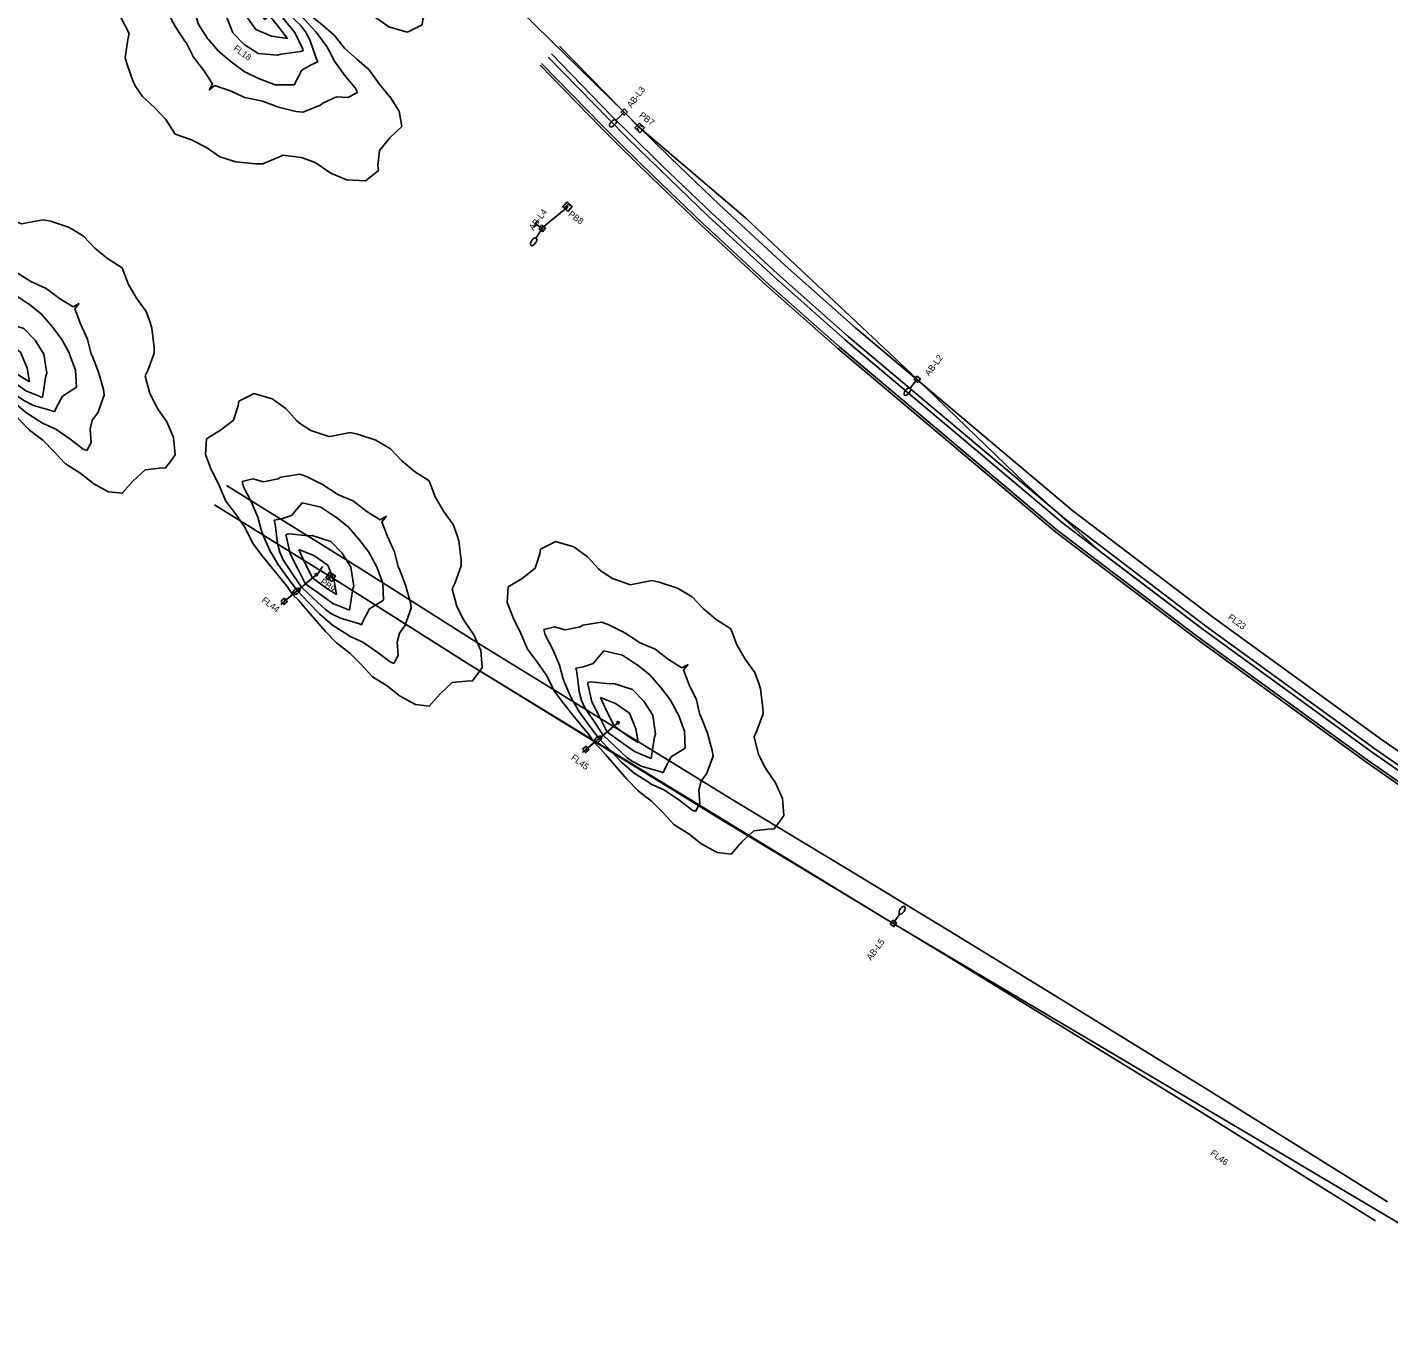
# Model space of a CAD drawing. Extents: x 1322666 to 1327584, y 458075 to 462260.
# Drawn here: x 1325587 to 1326187, y 459186 to 459766 of the extents above; entities that cross this region are included whole.
import ezdxf

# ---------------------------------------------------------------- set-up
doc = ezdxf.new("R2010")
doc.units = 0
for name, color, linetype in [('_CIVIL_CONSTRUCTION', 7, 'Continuous'), ('Default', 7, 'Continuous'), ('DR_P_Culvert', 7, 'Continuous'), ('DR_P_Culvert3D', 7, 'Continuous'), ('DR_X_Cells', 7, 'Continuous'), ('PF_X_Ground_Line', 7, 'Continuous'), ('UT_X_Cable_TV_FO', 7, 'Continuous'), ('UT_X_Misc_Cells', 7, 'Continuous'), ('UT_X_Oil', 7, 'Continuous')]:
    doc.layers.add(name, color=color, linetype=linetype)

# ---------------------------------------------------------------- blocks, each defined once
blk = doc.blocks.new('AGI32-IDj66arb-Project_1-LUMINAIRE-ERL2_19C330______Symbol')
at = {"layer": 'Default'}
for p, q in [((-0.03, 0), (0.03, 0)), ((0, 0.13), (0.24, 0.13)), ((0, -0.13), (0, 0.13)), ((0, 0.13), (0, 0.13)), ((0, 0.13), (0.24, 0.13)), ((0.24, 0.13), (0, 0.13)), ((0, -0.13), (0, 0.13)), ((0, 0.13), (0, 0.13)), ((0, 0.13), (0, -0.13)), ((0.24, 0.13), (0, 0.13)), ((0, 0.13), (0, -0.13)), ((0, -0.03), (0, 0.03)), ((0, 0.03), (0.03, 0)), ((0, -0.03), (0.03, 0)), ((0.24, 0.13), (0.24, -0.13)), ((0.24, 0.13), (0.24, 0.13)), ((0.24, 0.13), (0.24, 0.13)), ((0.24, 0.13), (0.24, -0.13)), ((0.24, -0.13), (0.24, 0.13)), ((0.24, -0.13), (0.24, 0.13)), ((0.24, -0.13), (0, -0.13)), ((0.24, -0.13), (0, -0.13)), ((0, -0.13), (0, -0.13)), ((0, -0.13), (0.24, -0.13)), ((0, -0.13), (0, -0.13)), ((0, -0.13), (0.24, -0.13)), ((0.24, -0.13), (0.24, -0.13)), ((0.24, -0.13), (0.24, -0.13))]:
    blk.add_line(p, q, dxfattribs=at)
blk = doc.blocks.new('AGI32-IDj66arb-Project_1-LUMINAIRE-ERL2_19C330______64-1')
at = {"layer": 'Default'}
blk.add_blockref('AGI32-IDj66arb-Project_1-LUMINAIRE-ERL2_19C330______Symbol', (0, 0), dxfattribs=at)
blk = doc.blocks.new('AGI32-IDj66arb-Project_1-LUMINAIRE-ERL2_19C330______Template1')
at = {"layer": 'Default'}
for p, q in [((9.14, 19.22), (10.58, 20.11)), ((10.58, 20.11), (10.97, 20.5)), ((10.97, 20.5), (12.6, 20.11)), ((12.6, 20.11), (12.8, 20.07)), ((12.8, 20.07), (13.99, 18.29)), ((4.29, 18.29), (5.49, 19.56)), ((5.49, 19.56), (7.31, 19.28)), ((7.31, 19.28), (9.14, 19.22)), ((3.66, 16.46), (4.29, 18.29)), ((13.99, 18.29), (14.48, 16.46)), ((3.25, 14.63), (3.66, 16.45)), ((3.66, 16.45), (3.66, 16.46)), ((14.48, 16.46), (14.57, 14.63)), ((2.69, 12.8), (3.25, 14.63)), ((14.57, 14.63), (14.63, 14.24)), ((14.63, 14.24), (15.08, 12.8)), ((2.59, 10.97), (2.69, 12.8)), ((4.85, 10.97), (5.23, 12.8)), ((5.23, 12.8), (5.49, 13.32)), ((5.49, 13.32), (6.62, 12.8)), ((6.62, 12.8), (7.31, 11.77)), ((15.08, 12.8), (16.17, 10.97)), ((2.44, 9.14), (2.59, 10.97)), ((4.29, 9.14), (4.85, 10.97)), ((7.31, 11.77), (8.8, 10.97)), ((8.8, 10.97), (9.14, 10.91)), ((9.14, 10.91), (10.97, 9.83)), ((16.17, 10.97), (16.46, 10.82)), ((16.46, 10.82), (18.29, 9.79)), ((10.97, 9.83), (11.39, 9.14)), ((18.29, 9.79), (18.8, 9.14)), ((2, 7.31), (2.44, 9.14)), ((3.47, 7.31), (3.66, 7.83)), ((3.66, 7.83), (4.29, 9.14)), ((5.27, 7.31), (5.49, 7.72)), ((5.49, 7.72), (6.19, 7.31)), ((11.39, 9.14), (12.17, 7.31)), ((18.8, 9.14), (19.94, 7.31)), ((1.89, 5.49), (2, 7.31)), ((2.95, 5.49), (3.47, 7.31)), ((4.09, 5.49), (5.27, 7.31)), ((6.19, 7.31), (7.31, 6.87)), ((7.31, 6.87), (9.14, 7.19)), ((9.14, 7.19), (10.42, 5.49)), ((12.17, 7.31), (12.76, 5.49)), ((19.94, 7.31), (20.11, 6.9)), ((20.11, 6.9), (20.59, 5.49)), ((1.86, 3.66), (1.89, 5.49)), ((2.64, 3.66), (2.95, 5.49)), ((3.66, 4.54), (4.09, 5.49)), ((4.43, 3.66), (5.39, 5.49)), ((5.39, 5.49), (5.49, 5.63)), ((5.49, 5.63), (5.75, 5.49)), ((5.75, 5.49), (7.31, 3.9)), ((10.42, 5.49), (10.97, 3.69)), ((12.76, 5.49), (12.8, 5.34)), ((12.8, 5.34), (13.64, 3.66)), ((20.59, 5.49), (20.69, 3.66)), ((1.85, 1.83), (1.86, 3.66)), ((2.53, 1.83), (2.64, 3.66)), ((3.22, 1.83), (3.42, 3.66)), ((3.42, 3.66), (3.66, 4.54)), ((4.03, 1.83), (4.43, 3.66)), ((5.05, 1.83), (5.49, 3.41)), ((5.49, 3.41), (6.36, 1.83)), ((7.31, 3.9), (7.65, 3.66)), ((7.65, 3.66), (8.83, 1.83)), ((10.97, 3.69), (10.98, 3.66)), ((10.98, 3.66), (11.36, 1.83)), ((13.64, 3.66), (14.06, 1.83)), ((20.69, 3.66), (21.05, 1.83)), ((1.83, 1.08), (1.85, 1.83)), ((2.41, 0), (2.53, 1.83)), ((3.01, 0), (3.22, 1.83)), ((3.66, 0.28), (4.03, 1.83)), ((4.62, 0), (5.05, 1.83)), ((6.36, 1.83), (6.85, 0)), ((8.83, 1.83), (8.98, 0)), ((11.36, 1.83), (11.4, 0)), ((14.06, 1.83), (14.63, 0.14)), ((21.05, 1.83), (21.63, 0)), ((1.73, 0), (1.83, 1.08)), ((3.62, 0), (3.66, 0.28)), ((14.63, 0.14), (15.4, 0)), ((1.83, -0.98), (1.73, 0)), ((1.85, -1.83), (1.83, -0.98)), ((2.55, -1.83), (2.41, 0)), ((3.25, -1.83), (3.01, 0)), ((3.66, -0.25), (3.62, 0)), ((4.07, -1.83), (3.66, -0.25)), ((5.07, -1.83), (4.62, 0)), ((6.85, 0), (6.29, -1.83)), ((8.98, 0), (8.72, -1.83)), ((11.4, 0), (11.31, -1.83)), ((14.63, -0.15), (14.04, -1.83)), ((15.4, 0), (14.63, -0.15)), ((21.63, 0), (20.99, -1.83)), ((1.88, -3.66), (1.85, -1.83)), ((2.67, -3.66), (2.55, -1.83)), ((3.47, -3.66), (3.25, -1.83)), ((4.53, -3.66), (4.07, -1.83)), ((5.49, -3.15), (5.07, -1.83)), ((6.29, -1.83), (5.49, -3.15)), ((8.72, -1.83), (7.6, -3.66)), ((11.31, -1.83), (10.97, -3.51)), ((14.04, -1.83), (13.56, -3.66)), ((20.99, -1.83), (20.7, -3.66)), ((1.89, -5.49), (1.88, -3.66)), ((2.97, -5.49), (2.67, -3.66)), ((3.66, -4.38), (3.47, -3.66)), ((4.15, -5.49), (3.66, -4.38)), ((5.49, -5.44), (4.53, -3.66)), ((7.31, -3.83), (5.49, -5.44)), ((7.6, -3.66), (7.31, -3.83)), ((10.94, -3.66), (10.29, -5.49)), ((10.97, -3.51), (10.94, -3.66)), ((13.56, -3.66), (12.8, -5.21)), ((20.7, -3.66), (20.55, -5.49)), ((2.03, -7.31), (1.89, -5.49)), ((3.54, -7.31), (2.97, -5.49)), ((5.37, -7.31), (4.15, -5.49)), ((10.29, -5.49), (9.14, -7.01)), ((12.73, -5.49), (12.12, -7.31)), ((12.8, -5.21), (12.73, -5.49)), ((20.55, -5.49), (20.11, -6.73)), ((2.46, -9.14), (2.03, -7.31)), ((3.66, -7.66), (3.54, -7.31)), ((5.49, -7.55), (5.37, -7.31)), ((5.91, -7.31), (5.49, -7.55)), ((7.31, -6.76), (5.91, -7.31)), ((9.14, -7.01), (7.31, -6.76)), ((12.12, -7.31), (11.3, -9.14)), ((19.86, -7.31), (18.68, -9.14)), ((20.11, -6.73), (19.86, -7.31)), ((2.61, -10.97), (2.46, -9.14)), ((4.35, -9.14), (3.66, -7.66)), ((4.89, -10.97), (4.35, -9.14)), ((11.3, -9.14), (10.97, -9.68)), ((18.68, -9.14), (18.29, -9.64)), ((10.97, -9.68), (9.14, -10.74)), ((18.29, -9.64), (16.46, -10.68)), ((2.71, -12.8), (2.61, -10.97)), ((5.29, -12.8), (4.89, -10.97)), ((7.31, -11.59), (6.44, -12.8)), ((8.15, -10.97), (7.31, -11.59)), ((9.14, -10.74), (8.15, -10.97)), ((15.87, -10.97), (14.99, -12.8)), ((16.46, -10.68), (15.87, -10.97)), ((3.3, -14.63), (2.71, -12.8)), ((5.49, -13.2), (5.29, -12.8)), ((6.44, -12.8), (5.49, -13.2)), ((14.99, -12.8), (14.63, -14.39)), ((3.66, -16.33), (3.3, -14.63)), ((14.6, -14.63), (14.44, -16.46)), ((14.63, -14.39), (14.6, -14.63)), ((3.68, -16.46), (3.66, -16.33)), ((4.41, -18.29), (3.68, -16.46)), ((14.44, -16.46), (13.9, -18.29)), ((5.49, -19.4), (4.41, -18.29)), ((13.9, -18.29), (12.8, -19.89)), ((7.31, -19.11), (5.49, -19.4)), ((9.14, -19.03), (7.31, -19.11)), ((10.75, -20.11), (9.14, -19.03)), ((10.97, -20.33), (10.75, -20.11)), ((11.9, -20.11), (10.97, -20.33)), ((12.8, -19.89), (11.9, -20.11))]:
    blk.add_line(p, q, dxfattribs=at)
blk = doc.blocks.new('AGI32-IDj66arb-Project_1-LUMINAIRE-ERL2_19C330______64')
at = {"layer": 'Default'}
for q in [(5.08, 0), (0, 0)]:
    blk.add_line((0, 0), q, dxfattribs=at)
for name, p in [('AGI32-IDj66arb-Project_1-LUMINAIRE-ERL2_19C330______Template1', (0, 0)), ('AGI32-IDj66arb-Project_1-LUMINAIRE-ERL2_19C330______64-1', (5.08, 0))]:
    blk.add_blockref(name, p, dxfattribs=at)

msp = doc.modelspace()

# ---------------------------------------------------------------- linework, layer by layer
at = {"layer": '_CIVIL_CONSTRUCTION'}
for p, q in [((1325849.94, 459728.51), (1325846.41, 459724.97)), ((1325813.8, 459677.27), (1325811.09, 459673.06)), ((1325979.09, 459610.77), (1325975.98, 459606.86)), ((1325968.53, 459370.86), (1325971.3, 459375.02))]:
    msp.add_line(p, q, dxfattribs=at)
for points in [[(1325851.36, 459728.51), (1325849.95, 459727.09), (1325848.53, 459728.51), (1325849.94, 459729.92)], [(1325815.18, 459677.57), (1325814.1, 459675.89), (1325812.41, 459676.97), (1325813.5, 459678.65)], [(1325980.5, 459610.93), (1325979.25, 459609.37), (1325977.69, 459610.61), (1325978.94, 459612.18)], [(1325967.14, 459370.59), (1325968.25, 459372.25), (1325969.91, 459371.14), (1325968.8, 459369.48)]]:
    msp.add_lwpolyline(points, close=True, dxfattribs=at)
for centre, major_axis in [((1325845, 459723.55), (-1.41, -1.42)), ((1325810.01, 459671.38), (-1.08, -1.68)), ((1325974.73, 459605.3), (-1.25, -1.56)), ((1325972.41, 459376.69), (1.11, 1.66))]:
    msp.add_ellipse(centre, major_axis=major_axis, ratio=0.5, dxfattribs=at)
at = {"layer": 'DR_P_Culvert'}
for p, q in [((1325700.02, 459512.81), (1325703.88, 459515.99)), ((1325832.99, 459447.56), (1325836.85, 459450.73))]:
    msp.add_line(p, q, dxfattribs=at)
for points in [[(1325698.61, 459512.95), (1325700.15, 459514.22), (1325701.42, 459512.68), (1325699.88, 459511.41)], [(1325831.58, 459447.7), (1325833.12, 459448.97), (1325834.39, 459447.42), (1325832.85, 459446.15)]]:
    msp.add_lwpolyline(points, close=True, dxfattribs=at)
for centre in [(1325705.43, 459517.26), (1325838.39, 459452)]:
    msp.add_ellipse(centre, major_axis=(1.55, 1.27), ratio=0.5, dxfattribs=at)
at = {"layer": 'DR_P_Culvert3D'}
for points in [[(1326566.25, 459192.34), (1326517.11, 459224.11), (1326405.22, 459297.16), (1326358.74, 459327.37), (1326312.61, 459357.21), (1326257.95, 459394.3), (1326180.82, 459447.88), (1326106.29, 459501.97), (1326044.54, 459548.88), (1325948.67, 459629.62), (1325917.51, 459657.17), (1325888.32, 459684.12), (1325866.8, 459704.73), (1325852.63, 459718.66), (1325844.52, 459726.77), (1325817.82, 459754.16)], [(1326568.96, 459196.54), (1326519.83, 459228.31), (1326407.95, 459301.35), (1326361.46, 459331.57), (1326315.37, 459361.38), (1326260.78, 459398.43), (1326183.72, 459451.96), (1326109.27, 459505.99), (1326047.67, 459552.79), (1325951.93, 459633.41), (1325920.86, 459660.88), (1325891.74, 459687.77), (1325870.28, 459708.32), (1325856.15, 459722.21), (1325848.08, 459730.28), (1325821.4, 459757.65)], [(1325812.81, 459749.27), (1325839.54, 459721.85), (1325847.7, 459713.68), (1325861.92, 459699.71), (1325883.52, 459679.02), (1325912.82, 459651.98), (1325944.09, 459624.32), (1326040.17, 459543.41), (1326102.12, 459496.35), (1326176.77, 459442.18), (1326253.99, 459388.53), (1326308.74, 459351.38), (1326354.94, 459321.5), (1326401.4, 459291.3), (1326513.3, 459218.24), (1326562.45, 459186.47)], [(1326562.99, 459187.31), (1326513.84, 459219.08), (1326401.95, 459292.13), (1326355.48, 459322.34), (1326309.3, 459352.21), (1326254.55, 459389.36), (1326177.35, 459442.99), (1326102.72, 459497.16), (1326040.79, 459544.19), (1325944.75, 459625.08), (1325913.49, 459652.72), (1325884.21, 459679.75), (1325862.62, 459700.43), (1325848.41, 459714.39), (1325840.25, 459722.55), (1325813.53, 459749.97)], [(1325816.39, 459752.76), (1325843.1, 459725.36), (1325851.23, 459717.24), (1325865.4, 459703.3), (1325886.95, 459682.67), (1325916.17, 459655.69), (1325947.36, 459628.11), (1326043.29, 459547.32), (1326105.1, 459500.37), (1326179.66, 459446.25), (1326256.82, 459392.66), (1326311.51, 459355.54), (1326357.66, 459325.7), (1326404.13, 459295.49), (1326516.02, 459222.44), (1326565.16, 459190.66)], [(1325785.2, 459494.57), (1325733.06, 459527.63), (1325674.6, 459563.9)], [(1325669.33, 459555.4), (1325727.74, 459519.16), (1325779.84, 459486.12)], [(1326186.4, 459248.21), (1326107.89, 459297.14), (1326046.63, 459334.91), (1325996.52, 459365.58), (1325949.39, 459394.16), (1325899.43, 459424.26), (1325785.2, 459494.57)], [(1325779.96, 459486.05), (1325894.23, 459415.72), (1325944.22, 459385.6), (1325991.32, 459357.04), (1326041.4, 459326.39), (1326102.62, 459288.64), (1326181.11, 459239.73)]]:
    msp.add_lwpolyline(points, dxfattribs=at)
at = {"layer": 'DR_X_Cells'}
for p, q in [((1325856.34, 459721.97), (1325857.05, 459721.27)), ((1325824.5, 459687.23), (1325825.23, 459686.56)), ((1325720.05, 459523.91), (1325720.9, 459523.39))]:
    msp.add_line(p, q, dxfattribs=at)
for points in [[(1325856.72, 459723.68), (1325858.87, 459721.58), (1325856.78, 459719.43), (1325854.63, 459721.53)], [(1325824.83, 459688.95), (1325827.04, 459686.92), (1325825, 459684.71), (1325822.8, 459686.74)], [(1325720.06, 459525.66), (1325722.61, 459524.08), (1325721.03, 459521.53), (1325718.48, 459523.11)]]:
    msp.add_lwpolyline(points, close=True, dxfattribs=at)
for points in [[(1325857.93, 459721.81), (1325857.03, 459722.69), (1325855.64, 459721.25), (1325856.53, 459720.38)], [(1325826.09, 459687.12), (1325825.17, 459687.97), (1325823.82, 459686.5), (1325824.74, 459685.65)], [(1325721.64, 459524.11), (1325720.58, 459524.76), (1325719.53, 459523.06), (1325720.59, 459522.4)]]:
    msp.add_lwpolyline(points, dxfattribs=at)
at = {"layer": 'PF_X_Ground_Line'}
msp.add_line((1325856.8, 459721.61), (1325849.94, 459728.51), dxfattribs=at)
for points in [[(1325404.84, 460354.12), (1325410.9, 460303.73), (1325518.28, 460144.22), (1325611.69, 460008.79), (1325708.15, 459878.81), (1325758.82, 459817.69), (1325849.94, 459728.51), (1325856.7, 459721.64), (1325856.7, 459721.64)], [(1325979.09, 459610.77), (1325903.44, 459681.87), (1325856.77, 459721.6)], [(1326549.86, 459204.14), (1326540.44, 459206.65), (1326404.13, 459295.49), (1326311.18, 459355.82), (1326256.82, 459392.66), (1326179.66, 459446.25), (1326105.1, 459500.37), (1326059.83, 459534.69), (1326026.64, 459564.84), (1325979.09, 459610.77)], [(1325968.53, 459370.86), (1325779.96, 459486.05), (1325720.55, 459523.68)], [(1326267.74, 459188.9), (1326255.73, 459199.5), (1326188.44, 459240.49), (1325968.53, 459370.86)]]:
    msp.add_lwpolyline(points, dxfattribs=at)
at = {"layer": 'UT_X_Cable_TV_FO'}
for p, q in [((1325849.94, 459728.51), (1325849.94, 459728.51)), ((1325825.02, 459686.71), (1325813.73, 459677.43))]:
    msp.add_line(p, q, dxfattribs=at)
at = {"layer": 'UT_X_Oil'}
for p, q in [((1325811.9, 459680.76), (1325809.94, 459677.71)), ((1325814.25, 459676.99), (1325810.88, 459679.17)), ((1325716.96, 459528.2), (1325715, 459525.16)), ((1325719.32, 459524.44), (1325715.94, 459526.61))]:
    msp.add_line(p, q, dxfattribs=at)

# ---------------------------------------------------------------- block references
at = {"layer": 'DR_P_Culvert'}
for p, xscale, yscale, rotation in [((1325742.41, 459856.67), 3.937000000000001, 3.9370000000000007, -140.18243234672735), ((1325704.02, 459786.28), 3.9370000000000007, 3.9370000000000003, -127.5957929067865), ((1325563.19, 459605.36), 3.937, 3.9370000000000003, 39.81756765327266), ((1325698.51, 459511.51), 3.937, 3.9370000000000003, 39.81756765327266), ((1325831.48, 459446.26), 3.937, 3.9370000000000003, 39.81756765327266)]:
    msp.add_blockref('AGI32-IDj66arb-Project_1-LUMINAIRE-ERL2_19C330______64', p, dxfattribs=dict(at, xscale=xscale, yscale=yscale, rotation=rotation))

# ---------------------------------------------------------------- texts
at = {"layer": 'UT_X_Misc_Cells'}
for s, rotation, p in [('FL18', 323.47593, (1325677.43, 459756.08)), ('AB-L3', 53.47593, (1325853.12, 459730.18)), ('PB7', 323.47593, (1325856.25, 459726.56)), ('AB-L4', 53.47593, (1325809.9, 459676.14)), ('PB8', 323.47593, (1325825, 459682.98)), ('AB-L2', 53.47593, (1325984.37, 459611.89)), ('PB9', 323.47593, (1325715.65, 459520.9)), ('FL44', 323.47593, (1325689.87, 459512.86)), ('FL23', 323.47593, (1326115.75, 459505.29)), ('FL45', 323.47593, (1325826.19, 459443.41)), ('AB-L5', 53.47593, (1325958.68, 459354.41)), ('FL46', 323.47593, (1326108, 459269.12))]:
    msp.add_text(s, height=2.8, rotation=rotation, dxfattribs=at).set_placement(p)

doc.saveas('drawing.dxf')
